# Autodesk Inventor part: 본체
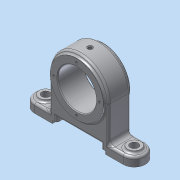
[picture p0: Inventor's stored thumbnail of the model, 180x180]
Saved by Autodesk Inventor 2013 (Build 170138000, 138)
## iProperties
Created: 2019-05
Part Number: 본체
Material: 알루미늄 6061
Document SubType Name: Modeling
Designer: dgall
Mass: 456.156 g
Surface Area: 319.371 cm^2
Volume: 168.323 cm^3
Density: 2.71 g/cm^3
Author: dgall
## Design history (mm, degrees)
sketch "스케치1"
  geometry: L1 (0, 0)-(150, 0); L2 (150, 0)-(150, 30); L3 (150, 30)-(0, 30); L4 (0, 30)-(0, 0)
  constraints: 8 end point, 2 parallel, 1 horizontal, 1 perpendicular
  dimensions: "d0" = 150 distance of L1.start L1.end; "d1" = 30 distance of L1.end L2.end
extrude "돌출1" new body sketch "스케치1" distance "d2" = 12; taper "d3" = 0 deg
node "작업 평면1"
sketch "스케치2"
  geometry: L1 (0, 0)-(150, 0) reference; L2 (0, 12)-(150, 12) reference; C1 r 40 at (75, 60); 1 further point
  constraints: 1 centre point, 1 midpoint, 1 vertical alignment
  dimensions: "d5" = 60 distance from line of L1 C1.centre; "d6" = 80 diameter of C1
extrude "돌출2" join sketch "스케치2" stored distance "d7" = 30; taper "d8" = 0 deg
sketch "스케치3"
  geometry: L1 (0, 0)-(150, 0) reference; L2 (150, 0)-(150, 12) reference; L3 (0, 12)-(150, 12) reference; L4 (0, 0)-(0, 12) reference; L5 (35, 60)-(35, 12); L6 (115, 60)-(115, 12); A1 r 40 centre (75, 60) between (35, 60) and (115, 60) reference; 1 further point
  constraints: 4 end point, 2 perpendicular, 2 point on circle, 2 point on line, 2 tangent
extrude "돌출3" join sketch "스케치3" stored distance "d9" = 30; taper "d10" = 0 deg
sketch "스케치4"
  geometry: L1 (0, 0)-(150, 0) reference; L2 (0, 0)-(0, 12) reference; L3 (39, 0)-(39, 4); L4 (39, 4)-(45, 4); L5 (45, 4)-(45, 10); L6 (45, 10)-(105, 10); L7 (105, 10)-(105, 4); L8 (105, 4)-(111, 4); L9 (111, 4)-(111, 0); 2 further points
  constraints: 14 end point, 5 parallel, 2 midpoint, 2 perpendicular, 2 point on line, 1 collinear, 1 vertical alignment
  dimensions: "d11" = 72 distance between parallel lines of L9 L3; "d13" = 60 distance between parallel lines of L7 L5; "d14" = 39 distance between parallel lines of L2 L3; "d15" = 10 distance between parallel lines of L1 L6; "d16" = 4 distance of L3.start L3.end
extrude "돌출4" cut sketch "스케치4" distance "d17" = 30; taper "d18" = 0 deg
fillet "모깎기1" dims "d28" = 15
sketch "스케치6"
  geometry: C1 r 9 at (15, 15); A1 r 15 centre (15, 15) between (15, 30) and (15, 0) reference; 1 further point
  constraints: 1 centre point, 1 coincident
  dimensions: "d29" = 18 diameter of C1
extrude "돌출5" join sketch "스케치6" distance "d31" = 3; taper "d32" = 0 deg
node "작업 평면2"
hole "구멍2" diameter "d36" = 11; stored, may be unused: countersink angle "d40" = 90 deg, drill point angle "d42" = 118 deg; dims "d34" = 10, "d35" = 10, "d37" = 6, "d38" = 4, "d39" = 2, "d41" = 8
hole "구멍3" diameter "d45" = 11; stored, may be unused: countersink angle "d49" = 90 deg, drill point angle "d51" = 118 deg; dims "d43" = 10, "d44" = 10, "d46" = 6, "d47" = 4, "d48" = 2, "d50" = 8
sketch "스케치8"
  geometry: C1 r 36 at (0, 0); A1 r 40 centre (0, 0) between (40, 0) and (-40, 0) reference; 1 further point
  constraints: 1 centre point, 1 coincident
  dimensions: "d63" = 72 diameter of C1
extrude "돌출7" join sketch "스케치8" distance "d67" = 3; taper "d68" = 0 deg
node "작업 평면3"
hole "구멍5" diameter "d71" = 52; stored, may be unused: countersink angle "d75" = 90 deg, drill point angle "d77" = 118 deg; dims "d72" = 6, "d73" = 4, "d74" = 2, "d76" = 8, "d87" = 10, "d88" = 10
sketch "스케치9" dims "d89" = 62
  geometry: L1 (0, 0)-(0, 31); C1 r 26 at (0, 0) reference; C2 r 36 at (0, 0) reference; 1 further point
  constraints: 2 end point, 1 coincident, 1 vertical, 1 vertical alignment, 2 other
node "작업점2"
hole "구멍7" diameter "d93" = 3.242; stored, may be unused: countersink angle "d97" = 90 deg, drill point angle "d99" = 118 deg; dims "d91" = 10, "d92" = 10, "d94" = 6, "d95" = 4, "d96" = 2, "d98" = 8
sketch "스케치10"
  geometry: L1 (0, 0)-(0, 26); C1 r 36 at (0, 0) reference; C2 r 1.5 at (0, 26); 2 further points
  constraints: 2 end point, 1 centre point, 1 coincident, 1 vertical, 1 vertical alignment, 1 other
  dimensions: "d103" = 3 diameter of C2
extrude "돌출8" cut sketch "스케치10" distance "d105" = 36; taper "d106" = 0 deg
node "작업 평면5"
sketch "스케치12"
  geometry: L1 (0, 0)-(-75, 0); L2 (-35, 30)-(-35, 0) reference; L3 (-115, 0)-(-35, 0) reference; L4 (-115, 30)-(-115, 0) reference; L5 (-35, 30)-(-115, 30) reference; L6 (-35, 15)-(-115, 15); L7 (-75, 0)-(-75, 15)
  constraints: 6 end point, 3 midpoint, 1 horizontal
  dimensions: "d108" = 75 distance of L1.start L1.end
  node "투영된 루프3"
node "작업점3"
hole "구멍8" sketch "스케치12" diameter "d109" = 4.917; stored, may be unused: countersink angle "d113" = 90 deg, drill point angle "d115" = 118 deg; dims "d110" = 8, "d111" = 7, "d112" = 1, "d114" = 10
chamfer "모따기1" distance "d116" = 1; stored, may be unused: second distance "d117" = 2, angle "d118" = 45 deg
fillet "모깎기2" dims "d119" = 3
fillet "모깎기3" dims "d120" = 3
fillet "모깎기4" dims "d121" = 3
fillet "모깎기5" dims "d122" = 3
fillet "모깎기6" dims "d123" = 6
sketch "스케치13"
  geometry: L1 (66, -6)-(6, -6) reference; A1 r 39 centre (36, -56) between (73, -43.671) and (-1, -43.671) reference; 2 further points
  constraints: 1 vertical alignment, 1 other
  dimensions: "d124" = 7 distance from line of point (36, -13) L1
feature "엠보싱1" sketch "스케치13" dims "d125" = 0.5, "d126" = 0
node "솔리드1"
mirror "대칭1"
mirror "대칭2"
pattern_circular "원형 패턴1" dims angle "d101" = 360 deg
mirror "대칭3"
node "투영된 루프1"
node "투영된 루프2"
node "작업 평면4"
other parameters: "d4" = -15, "d33" = 75
